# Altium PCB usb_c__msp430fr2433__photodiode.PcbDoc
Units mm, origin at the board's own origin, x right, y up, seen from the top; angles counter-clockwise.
Board outline 56 x 30 mm, 2 copper layers (Top, Bottom), stack 0 mm thick; 27 components, 18 nets, 131 pads, 47 vias.
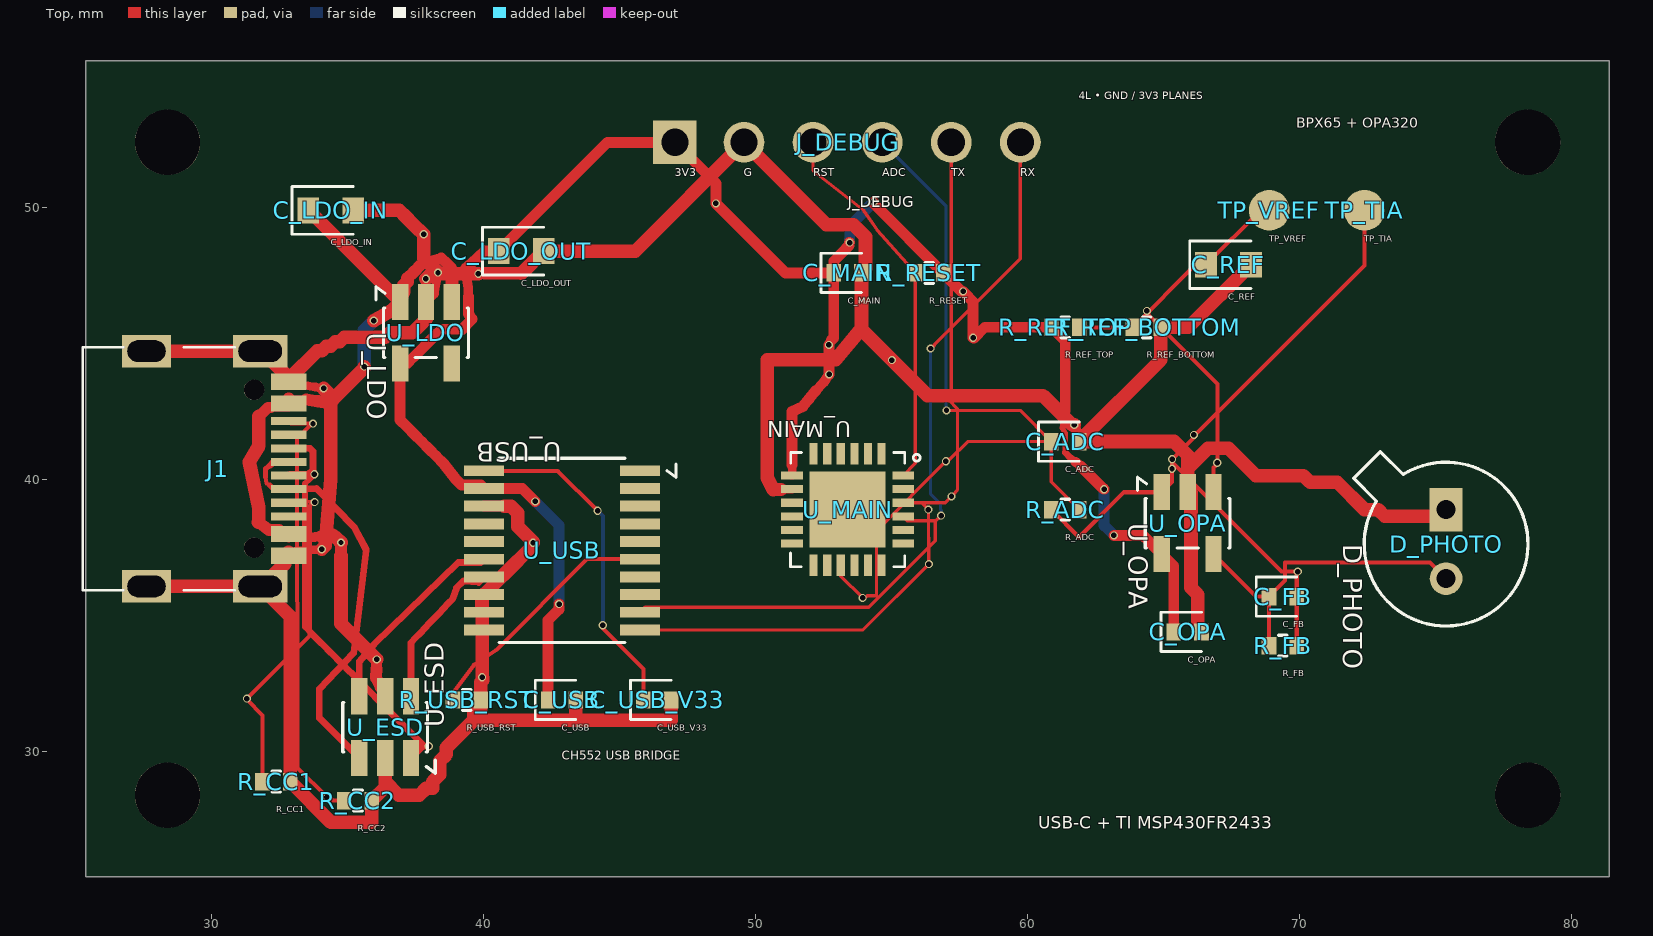
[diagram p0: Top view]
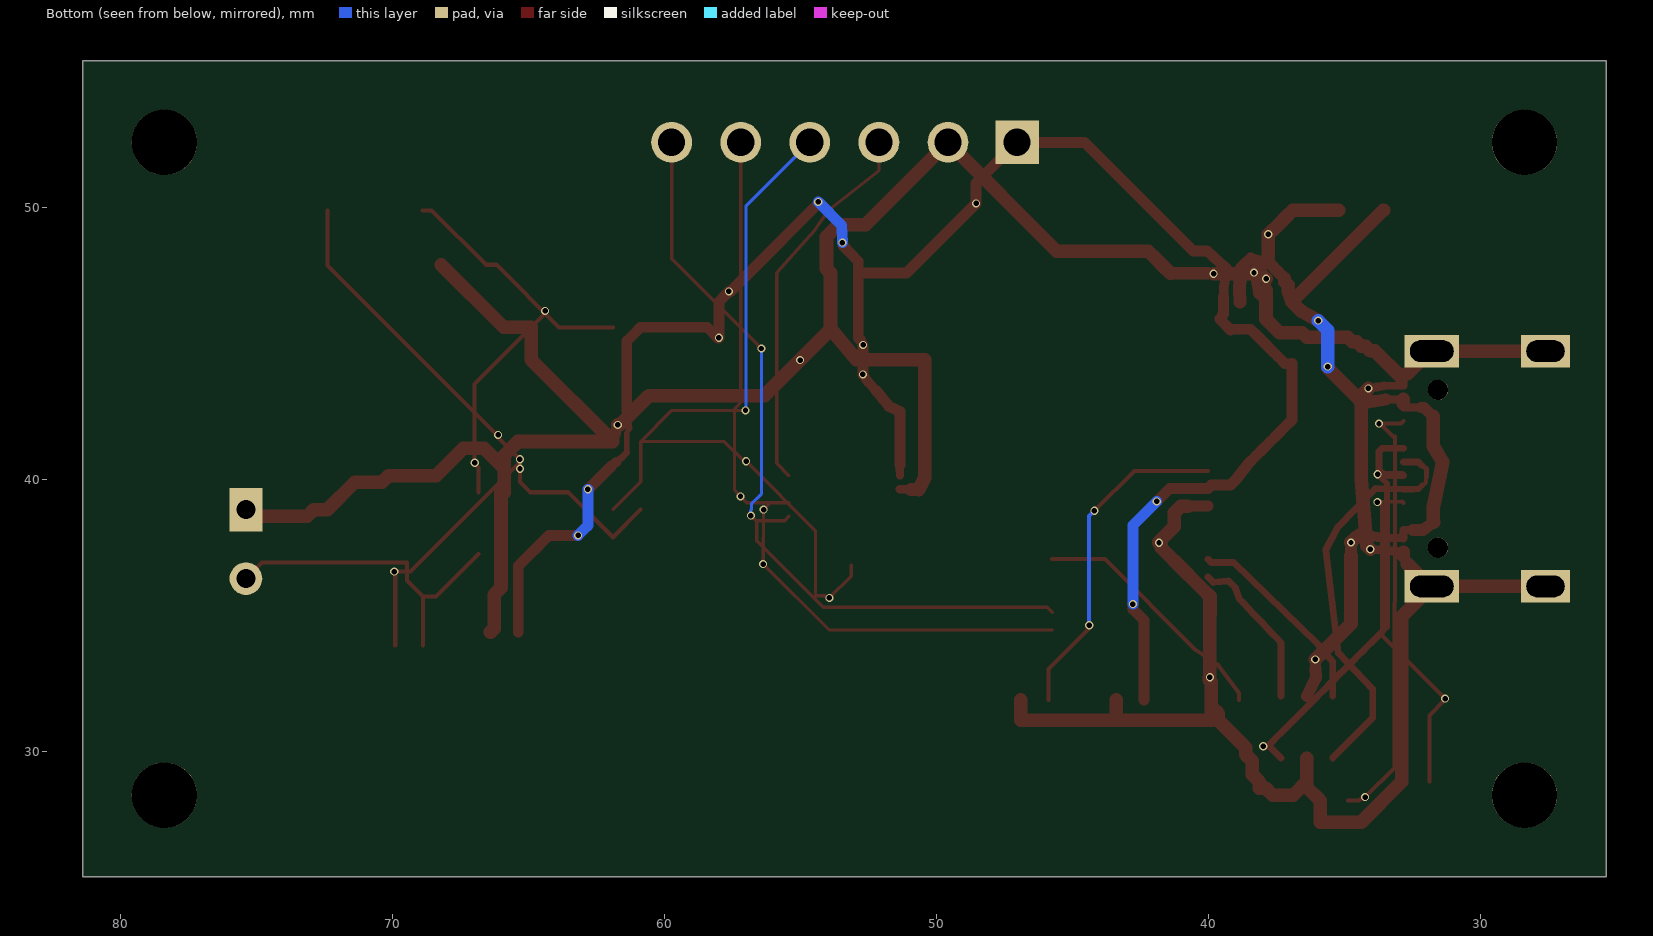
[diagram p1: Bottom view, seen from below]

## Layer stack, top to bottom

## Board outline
25.4,55.4 81.4,55.4 81.4,25.4 25.4,25.4

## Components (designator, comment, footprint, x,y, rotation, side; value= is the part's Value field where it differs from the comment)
C_ADC "" TSCIRCUIT-1.5600x0.6400mm 61.4,41.4 r0 top
C_FB "" TSCIRCUIT-1.5600x0.6400mm 69.4,35.7 r0 top
C_LDO_IN "" TSCIRCUIT-2.4500x0.9500mm 34.4,49.9 r0 top
C_LDO_OUT "" TSCIRCUIT-2.4500x0.9500mm 41.4,48.4 r0 top
C_MAIN "" TSCIRCUIT-1.5600x0.6400mm 53.4,47.6 r0 top
C_OPA "" TSCIRCUIT-1.5600x0.6400mm 65.9,34.4 r0 top
C_REF "" TSCIRCUIT-2.4500x0.9500mm 67.4,47.9 r0 top
C_USB "" TSCIRCUIT-1.5600x0.6400mm 42.9,31.9 r0 top
C_USB_V33 "" TSCIRCUIT-1.5600x0.6400mm 46.4,31.9 r0 top
D_PHOTO "" TSCIRCUIT-1.2000x3.9400mm 75.4,37.73 r270 top
J1 "" TSCIRCUIT-6.7732x9.8502mm 30.113,40.4 r90 top
J_DEBUG "" TSCIRCUIT-14.2000x1.5000mm 53.4,52.4 r0 top
R_ADC "" TSCIRCUIT-1.5600x0.6400mm 61.4,38.9 r0 top
R_CC1 "" TSCIRCUIT-1.5600x0.6400mm 32.4,28.9 r0 top
R_CC2 "" TSCIRCUIT-1.5600x0.6400mm 35.4,28.2 r0 top
R_FB "" TSCIRCUIT-1.5600x0.6400mm 69.4,33.9 r0 top
R_REF_BOTTOM "" TSCIRCUIT-1.5600x0.6400mm 64.4,45.6 r0 top
R_REF_TOP "" TSCIRCUIT-1.5600x0.6400mm 61.4,45.6 r0 top
R_RESET "" TSCIRCUIT-1.5600x0.6400mm 56.4,47.6 r0 top
R_USB_RST "" TSCIRCUIT-1.5600x0.6400mm 39.4,31.9 r0 top
TP_TIA "" TSCIRCUIT-1.5000x1.5000mm 72.4,49.9 r0 top
TP_VREF "" TSCIRCUIT-1.5000x1.5000mm 68.9,49.9 r0 top
U_ESD "" TSCIRCUIT-2.5000x3.6000mm#1 36.4,30.9 r90 top
U_LDO "" TSCIRCUIT-2.5000x3.6000mm#2 37.9,45.4 r270 top
U_MAIN "" TSCIRCUIT-4.8833x4.8963mm 53.4,38.9 r180 top
U_OPA "" TSCIRCUIT-2.5000x3.6000mm#2 65.9,38.4 r270 top
U_USB "" TSCIRCUIT-7.2000x6.2500mm 42.9,37.4 r180 top

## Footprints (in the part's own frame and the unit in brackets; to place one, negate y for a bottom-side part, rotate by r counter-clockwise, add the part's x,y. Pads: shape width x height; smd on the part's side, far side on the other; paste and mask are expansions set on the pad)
TSCIRCUIT-1.2000x3.9400mm [mm]
  rect 1.6x1.2 hole 0.7: 1(-1.17,0)
  round 1.2 hole 0.7: 2(1.37,0)
  silkscreen extent -3.3,-3.4 3.11,3.01
TSCIRCUIT-1.5000x1.5000mm [mm]
  round 1.5 smd: 1(0,0)
TSCIRCUIT-1.5600x0.6400mm [mm]
  rect 0.54x0.64 smd: 1(-0.51,0) 2(0.51,0)
  silkscreen extent -0.98,-0.72 0.51,0.72
TSCIRCUIT-2.4500x0.9500mm [mm]
  rect 0.8x0.95 smd: 1(-0.825,0) 2(0.825,0)
  silkscreen extent -1.43,-0.87 0.82,0.87
TSCIRCUIT-2.5000x3.6000mm#1 [mm]
  rect 1.325x0.6 smd: 1(-1.137,-0.95) 2(-1.137,0) 3(-1.137,0.95) 4(1.138,0.95) 5(1.138,0) 6(1.138,-0.95)
  silkscreen extent -1.69,-1.84 0.91,1.56
TSCIRCUIT-2.5000x3.6000mm#2 [mm]
  rect 1.325x0.6 smd: 1(-1.137,-0.95) 2(-1.137,0) 3(-1.137,0.95) 4(1.138,0.95) 5(1.138,-0.95)
  silkscreen extent -1.69,-1.84 0.91,1.56
TSCIRCUIT-4.8833x4.8963mm [mm]
  rect 0.8x0.3 smd: 1(-2.042,-1.25) 2(-2.042,-0.75) 3(-2.042,-0.25) 4(-2.042,0.25) 5(-2.042,0.75) 6(-2.042,1.25) 13(2.042,1.25) 14(2.042,0.75) 15(2.042,0.25) 16(2.042,-0.25) 17(2.042,-0.75) 18(2.042,-1.25)
  rect 0.3x0.8 smd: 7(-1.25,2.048) 8(-0.75,2.048) 9(-0.25,2.048) 10(0.25,2.048) 11(0.75,2.048) 12(1.25,2.048) 19(1.25,-2.048) 20(0.75,-2.048) 21(0.25,-2.048) 22(-0.25,-2.048) 23(-0.75,-2.048) 24(-1.25,-2.048)
  rect 2.8x2.8 smd: 25(-0.001,0.001)
  silkscreen extent -2.67,-2.1 2.1,2.1
TSCIRCUIT-6.7732x9.8502mm [mm]
  rect 0.3x1.3 smd: 1(-3.35,-2.737) 2(-3.05,-2.737) 3(-2.55,-2.737) 4(-2.25,-2.737) 5(-1.75,-2.737) 6(-1.25,-2.737) 7(-0.75,-2.737) 8(-0.25,-2.737) 9(0.25,-2.737) 10(0.75,-2.737) 11(1.25,-2.737) 12(1.75,-2.737) 13(2.55,-2.737) 14(2.25,-2.737) 15(3.35,-2.737) 16(3.05,-2.737)
  rect 1.2x2 hole 0.8 slot 1.6 at 90 deg: 17(-4.325,-1.693) 18(4.325,-1.693)
  rect 1.2x1.8 hole 0.8 slot 1.4 at 90 deg: 19(4.325,2.487) 20(-4.325,2.487)
  round 0.75 hole 0.75 unplated: NPTH-1(-2.9,-1.468) NPTH-2(2.9,-1.468)
  silkscreen extent -4.47,-0.75 4.47,4.83
TSCIRCUIT-7.2000x6.2500mm [mm]
  rect 1.475x0.4 smd: 1(-2.862,-2.925) 2(-2.862,-2.275) 3(-2.862,-1.625) 4(-2.862,-0.975) 5(-2.862,-0.325) 6(-2.862,0.325) 7(-2.862,0.975) 8(-2.862,1.625) 9(-2.862,2.275) 10(-2.862,2.925) 11(2.863,2.925) 12(2.863,2.275) 13(2.863,1.625) 14(2.863,0.975) 15(2.863,0.325) 16(2.863,-0.325) 17(2.863,-0.975) 18(2.863,-1.625) 19(2.863,-2.275) 20(2.863,-2.925)
  silkscreen extent -4.19,-3.39 2.31,3.38
TSCIRCUIT-14.2000x1.5000mm [mm]
  rect 1.6x1.6 hole 1: 1(-6.35,0)
  round 1.5 hole 1: 2(-3.81,0) 3(-1.27,0) 4(1.27,0) 5(3.81,0) 6(6.35,0)

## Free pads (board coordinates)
  round 2.4 hole 2.4 unplated: NPTH-3(28.4,28.4) NPTH-4(78.4,52.4) NPTH-5(78.4,28.4) NPTH-6(28.4,52.4)

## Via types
v1: diameter 0.3, hole 0.2, Top to Bottom, 47 vias

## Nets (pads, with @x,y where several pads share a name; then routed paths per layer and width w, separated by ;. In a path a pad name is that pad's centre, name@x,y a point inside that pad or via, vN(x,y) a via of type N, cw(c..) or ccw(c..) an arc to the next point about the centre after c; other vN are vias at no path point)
ADC_IN: C_ADC.1 J_DEBUG.4 R_ADC.2 U_MAIN.10 | length 30.3
  Top w0.12: U_MAIN.10 53.15,36.452 v1(53.95,35.652) 54.043,35.652 54.12,35.729 54.465,35.729 54.465,38.126 v1(57.012,40.673) 57.088,40.749 57.16,40.749 57.811,41.4 C_ADC.1 ; v1(57.034,42.544) 59.746,42.544 C_ADC.1 ; R_ADC.2 60.89,39.92 C_ADC.1
  Bottom w0.12: J_DEBUG.4 57.02,50.05 57.02,42.624 57.02,42.558 v1(57.034,42.544)
GND: C_ADC.2 C_LDO_IN.2 C_LDO_OUT.2 C_MAIN.2 C_OPA.2 C_REF.2 C_USB.2 C_USB_V33.2 D_PHOTO.1 J1.1 J1.2 J1.15 J1.16 J1.17 J1.18 J1.19 J1.20 J_DEBUG.2 R_CC1.2 R_CC2.2 R_REF_BOTTOM.2 R_USB_RST.2 U_ESD.2 U_LDO.2 U_MAIN.17 U_OPA.2 U_USB.18 | length 150.8
  Top w0.275: J1.16 33.197,43.45 33.545,43.45
  Top w0.288: J1.16 J1.16@32.849,43.6
  Top w0.3: J1.1@32.699,36.9 J1.1 J1.1@32.849,37.2 ; 32.699,43.9 J1.15 ; J1.16@32.849,43.6 J1.15 ; J1.15@32.917,43.75 J1.15
  Top w0.312: 33.545,43.45 33.841,43.401 ; v1(39.828,47.57) 40.062,47.587
  Top w0.318: U_MAIN.17@50.958,39.641 51.012,39.642 U_MAIN.17
  Top w0.325: J1.2 33.256,37.38 33.664,37.41 v1(34.071,37.44) ; 33.841,43.401 v1(34.137,43.351) ; 38.2,46.837 38.271,47.224 v1(38.343,47.611)
  Top w0.35: v1(37.899,47.384) 37.899,46.962 U_LDO.2@37.9,46.961 ; U_LDO.2 38.2,46.837
  Top w0.4: U_USB.18 U_USB.18@40.775,39.025 ; v1(61.73,42.012) 61.82,41.706 C_ADC.2
  Top w0.475: J1.1@32.849,37.2 J1.2 ; 40.062,47.587 40.512,47.587 40.962,47.587 41.412,47.587 ; 50.666,39.634 U_MAIN.17@50.958,39.641
  Top w0.5: J1.20 J1.17 ; J1.19 J1.18 31.874,44.725 32.474,44.125 32.699,43.9 ; J1.1@32.699,36.9 32.474,36.675 31.874,36.075 J1.17 ; J1.15@32.917,43.75 33.9,44.733 34.067,44.733 34.233,44.9 34.4,44.9 34.567,45.067 34.733,45.067 34.9,45.233 36.4,45.233 36.567,45.4 37.4,45.4 37.9,45.9 U_LDO.2 U_LDO.2@37.9,46.961 ; v1(34.071,37.44) 34.2,37.569 34.2,37.6 34.4,40 34.4,43.089 v1(34.137,43.351) ; C_LDO_IN.2 35.647,49.9 36.07,49.9 36.492,49.9 36.915,49.9 37.165,49.65 37.415,49.4 37.664,49.15 37.687,49.15 v1(37.815,49.022) 37.815,48.139 v1(38.343,47.611) ; v1(37.899,47.384) 38.085,47.57 v1(39.828,47.57) ; 40.775,39.025 41.025,39.025 41.275,38.775 41.275,38.275 41.834,37.716 v1(41.834,37.68) 41.753,37.599 41.753,37.5 41.454,37.201 41.155,36.902 40.856,36.602 40.557,36.303 40.258,36.004 39.959,35.705 39.96,35.211 39.961,34.716 39.962,34.222 39.963,33.727 39.964,33.233 v1(39.965,32.738) 39.981,32.722 39.981,32.62 39.91,32.55 39.91,32.225 R_USB_RST.2 ; 41.412,47.587 41.683,47.858 41.954,48.129 C_LDO_OUT.2 45.59,48.4 J_DEBUG.2 52.621,49.369 53.619,49.369 54.056,48.931 54.056,48.275 54.056,47.746 C_MAIN.2 ; C_USB_V33.2 46.91,31.15 43.41,31.15 ; 50.666,39.634 50.447,40.072 50.447,44.41 52.963,44.41 53.91,45.556 53.91,45.965 53.91,46.374 53.91,46.783 53.91,47.191 C_MAIN.2 ; v1(61.73,42.012) 61.656,42.012 60.578,43.089 56.337,43.089 v1(55.03,44.396) 53.91,45.516 C_MAIN.2 ; C_OPA.2 66.4,34.4 66.275,34.525 66.275,35.775 66.025,36.025 66.025,39.525 65.912,39.525 U_OPA.2 ; C_REF.2 65.925,45.6 R_REF_BOTTOM.2 64.91,44.4 C_ADC.2 65.4,41.4 65.9,40.9 U_OPA.2 ; D_PHOTO.1 75.152,38.652 74.654,38.652 74.155,38.652 73.656,38.652 73.158,38.652 73.148,38.652 72.9,38.9 72.4,38.9 71.4,39.9 70.4,39.9 70.15,40.15 68.4,40.15 67.4,41.15 66.65,41.15 65.9,40.4 U_OPA.2 ; J1.17 32.91,34.971 R_CC1.2 34.41,27.4 35.91,27.4 R_CC2.2 36.4,28.69 U_ESD.2 36.4,28.9 36.9,28.4 37.65,28.4 37.9,28.65 38.15,28.65 38.15,28.9 38.4,29.15 38.4,29.65 38.65,29.9 38.65,30.15 39.65,31.15 39.65,31.4 39.91,31.66 R_USB_RST.2 ; R_USB_RST.2 39.91,31.15 43.41,31.15 ; 43.41,31.15 C_USB.2 43.41,31.15
MAIN_RESET: J_DEBUG.3 R_RESET.1 U_MAIN.1 | length 14
  Top w0.12: J_DEBUG.3 52.13,51.36 53.981,49.904 54.486,49.17 R_RESET.1 55.89,40.598 U_MAIN.1
PD_SUM: C_FB.1 D_PHOTO.2 R_FB.1 U_OPA.4 | length 12.2
  Top w0.15: U_OPA.4 68.412,35.7 C_FB.1 ; R_FB.1 C_FB.1 ; D_PHOTO.2 74.804,36.956 69.479,36.96 69.479,36.289 C_FB.1
TIA_OUT: C_FB.2 R_ADC.1 R_FB.2 TP_TIA.1 U_OPA.1 | length 29.1
  Top w0.15: R_ADC.1 61.908,37.882 63.564,39.538 U_OPA.1 ; R_FB.2 C_FB.2 69.91,36.45 69.91,36.584 v1(69.95,36.619) 69.35,36.624 65.344,40.63 65.344,40.736 v1(65.325,40.4) 65.33,39.917 ; TP_TIA.1 72.4,47.873 66.24,41.713 66.202,41.713 v1(66.131,41.642) 66.131,41.551 65.34,40.76 v1(65.33,40.75) 65.33,39.917 ; U_OPA.1 65.33,39.917 ; U_OPA.1 65.33,39.917
UART_MAIN_RX: J_DEBUG.6 U_MAIN.4 U_USB.9 | length 30.7
  Top w0.12: U_USB.9 45.949,35.311 54.181,35.311 56.626,37.757 56.626,38.492 55.6,38.492 U_MAIN.4 55.615,38.477 55.619,38.477 56.619,38.477 v1(56.835,38.677) ; v1(56.451,44.82) 56.588,44.927 56.588,44.96 59.75,48.121 J_DEBUG.6
  Bottom w0.12: v1(56.451,44.82) 56.451,39.47 56.817,39.103 56.817,38.9 56.85,38.868 56.85,38.708 v1(56.835,38.677)
UART_MAIN_TX: J_DEBUG.5 U_MAIN.3 U_USB.10 | length 29.7
  Top w0.12: U_USB.10 53.966,34.475 v1(56.387,36.896) ; v1@56.388,36.898 56.383,36.903 v1(56.371,38.9) 56.349,38.928 56.127,39.15 U_MAIN.3 56.985,39.15 v1(57.219,39.384) 57.349,39.514 57.349,39.529 57.435,39.615 57.435,39.744 57.435,42.611 57.342,42.705 57.21,42.836 J_DEBUG.5
USB_BRIDGE_RESET: R_USB_RST.1 U_USB.6 | length 9.2
  Top w0.15: R_USB_RST.1 38.887,32.142 39.675,33.2 40.484,33.737 43.825,37.075 U_USB.6
USB_BRIDGE_V33: C_USB_V33.1 U_USB.20 | length 12.4
  Top w0.15: U_USB.20 42.743,40.325 v1(44.211,38.857) ; v1(44.4,34.646) 44.4,34.533 45.89,33.043 C_USB_V33.1
  Bottom w0.15: v1(44.211,38.857) 44.234,38.834 44.234,38.826 44.4,38.661 v1(44.4,34.646)
USB_CC1: J1.6 R_CC1.1 | length 12.6
  Top w0.15: R_CC1.1 31.89,31.333 31.312,31.91 31.312,31.945 v1(31.319,31.952) 33.626,34.259 33.626,39.013 33.626,39.026 33.782,39.182 v1(33.808,39.176) 32.899,39.2 J1.6
USB_CC2: J1.12 R_CC2.1 | length 16.1
  Top w0.15: J1.12 32.938,42.061 v1(33.746,42.061) 33.735,42.05 33.69,42.05 33.231,41.591 33.165,41.591 33.179,29.401 v1(34.26,28.33) 34.325,28.265 34.417,28.265 34.482,28.2 R_CC2.1
USB_DM_MCU: U_ESD.4 U_USB.15 | length 7.4
  Top w0.25: U_ESD.4 35.449,33.31 36,33.95 39.086,36.956 39.916,36.954 U_USB.15
USB_DM_PORT: J1.7 J1.9 U_ESD.3 | length 15.1
  Top w0.156: 32,40.1 32.037,39.865 32.157,39.789
  Top w0.188: 32,40.1 32.003,40.2 32,40.4 32.176,40.529
  Top w0.2: 32.157,39.789 J1.7@32.296,39.65
  Top w0.225: J1.7@32.296,39.65 J1.7@32.48,39.65
  Top w0.25: 32.176,40.529 32.297,40.65 32.481,40.65 32.665,40.65 J1.9 ; J1.7@32.48,39.65 32.665,39.65 J1.7 33.87,39.67 35.267,38.24 35.704,37.424 35.241,33.621 33.978,32.307 33.978,31.234 U_ESD.3
USB_DP_MCU: U_ESD.6 U_USB.14 | length 5.8
  Top w0.25: U_ESD.6 37.35,32.283 37.35,32.529 37.35,32.775 37.35,33.021 37.35,33.267 37.35,33.513 37.35,33.759 37.35,34.005 37.521,34.185 37.691,34.364 37.862,34.544 38.033,34.724 38.204,34.903 38.374,35.083 38.545,35.262 38.716,35.442 38.887,35.621 39.025,36.025 39.275,36.275 39.836,36.224 39.937,36.324 U_USB.14
USB_DP_PORT: J1.8 J1.10 U_ESD.1 | length 16.5
  Top w0.212: 33.459,34.582 33.456,34.595 33.456,34.834 33.456,35.073 33.456,35.312 33.455,35.551 33.455,35.79 33.455,36.029 33.454,36.268 33.454,36.507 33.454,36.747 33.453,36.986 33.453,37.225 33.453,37.464 33.452,37.703 33.452,37.942 33.452,38.181 33.451,38.42 33.451,38.659 33.451,38.898 33.45,39.137 33.45,39.376 33.45,39.615 33.449,39.854 33.625,40.027 v1(33.8,40.2)
  Top w0.219: 33.459,34.582 33.634,34.407
  Top w0.25: J1.10 33.637,41.15 33.746,41.042 33.746,40.359 33.587,40.2 32.899,40.2 J1.8 33.099,40.15 33.349,40.15 33.599,40.15 33.75,40.15 v1(33.8,40.2) ; 33.634,34.407 33.809,34.232 33.984,34.056 34.16,33.881 34.335,33.706 34.51,33.531 34.685,33.355 34.86,33.18 35.035,33.005 35.21,32.829 35.385,32.654 35.56,32.479 35.736,32.304 35.911,32.128 36.086,31.953 36.261,31.778 36.436,31.602 36.611,31.427 36.786,31.252 36.961,31.076 37.136,30.901 37.312,30.726 37.487,30.551 37.662,30.375 37.837,30.2 v1(38,30.2) 37.788,30.2 37.642,30.054 37.496,29.908 U_ESD.1
VBUS5: C_LDO_IN.1 J1.3 J1.4 J1.13 J1.14 U_ESD.5 U_LDO.1 U_LDO.3 | length 30.8
  Top w0.3: J1.14@32.199,42.65 J1.14 J1.14@32.849,42.8 ; J1.4@32.491,38.15 J1.4 J1.3@32.849,38 ; J1.3 32.945,37.861 33.037,37.85 33.13,37.85 33.224,37.85 33.318,37.85 33.412,37.85 33.499,37.85 ; J1.13 32.943,42.95 33.037,42.95 33.13,42.95 33.224,42.95 33.318,42.95 33.412,42.95 33.499,42.95
  Top w0.31: J1.3 J1.3@32.849,38
  Top w0.375: 33.499,37.85 33.505,37.85 33.984,37.906
  Top w0.4: 31.757,42.32 31.838,42.4 32.087,42.65 J1.14@32.199,42.65 ; 33.984,37.906 34.462,37.962 ; 36.079,33.053 v1(36.087,33.391) ; 37.713,47.9 38.088,48.025 38.463,48.15 38.65,47.962 38.837,47.775 38.858,47.384
  Top w0.425: 34.775,37.196 v1(34.775,37.689)
  Top w0.437: 31.744,38.431 32.134,38.15 J1.4@32.491,38.15 ; 36.079,33.053 36.07,32.714 36.235,32.376 U_ESD.5 ; 37.213,47.4 37.463,47.65 37.713,47.9
  Top w0.45: 33.499,42.95 33.505,42.95 33.937,42.878 34.369,42.806 ; 37.213,47.275 37.213,47.4
  Top w0.475: U_LDO.3 38.878,46.992 38.858,47.384
  Top w0.5: 31.744,38.431 31.757,38.527 31.757,38.98 31.4,40.65 31.757,41.244 31.757,42.32 ; J1.13@32.849,42.8 J1.13@32.849,42.95 ; C_LDO_IN.1 33.587,49.9 U_LDO.1 ; 34.369,42.806 34.546,43.018 35.631,44.103 v1(35.631,44.154) ; 34.462,37.962 34.599,37.859 34.605,37.859 v1(34.775,37.689) ; 34.775,37.196 34.775,36.704 34.775,34.703 v1(36.087,33.391) ; v1(35.982,45.844) 36.592,46.191 36.603,46.191 U_LDO.1 ; 37.213,47.275 37.081,47.144 37.081,46.906 U_LDO.1
  Bottom w0.5: v1(35.631,44.154) 35.631,45.493 v1(35.982,45.844)
VCC_3V3: C_LDO_OUT.1 C_MAIN.1 C_OPA.1 C_USB.1 J_DEBUG.1 R_REF_TOP.1 R_RESET.2 U_LDO.5 U_MAIN.18 U_OPA.5 U_USB.19 | length 74
  Top w0.2: 61.3,41.9 61.4,41.7 61.4,41.35 61.4,41
  Top w0.212: 61.3,41.9 61.35,42.213
  Top w0.25: 61.35,42.213 61.399,42.526 ; 61.4,41 61.6,40.8 61.778,40.653
  Top w0.3: U_MAIN.18 U_MAIN.18@51.358,40.3
  Top w0.312: 51.358,40.3 51.358,40.543
  Top w0.35: 39.4,47.4 39.458,47.05 39.458,46.729
  Top w0.363: 52.236,43.281 52.5,43.55 v1(52.719,43.87) ; 61.778,40.653 61.956,40.505
  Top w0.375: v1(52.713,44.955) 52.812,45.132
  Top w0.387: 39.342,47.75 39.4,47.4
  Top w0.4: 39.342,47.75 39.583,47.967 39.824,48.183 40.066,48.4 40.32,48.4 C_LDO_OUT.1 44.575,52.4 J_DEBUG.1 48.557,50.893 v1(48.557,50.154) 48.657,50.054 51.111,47.6 C_MAIN.1 ; 39.458,46.729 39.458,46.408 39.458,46.088 39.6,45.9 39.2,45.5 39.187,45.53 38.827,45.53 38.467,45.53 38.214,45.276 37.96,45.023 37.706,44.769 37.453,44.516 37.199,44.262 U_LDO.5 36.95,43.917 36.95,43.571 36.95,43.226 36.95,42.88 36.95,42.535 36.95,42.189 37.216,41.924 37.481,41.658 37.747,41.393 38.012,41.127 38.278,40.862 38.543,40.596 39,40 39.2,39.8 39.34,39.8 39.626,39.8 39.913,39.8 U_USB.19 41.44,39.675 v1(41.916,39.199) ; C_USB.1 42.39,34.829 42.794,35.233 v1(42.794,35.424) ; 51.358,40.543 51.358,40.936 51.358,41.33 51.358,41.723 51.358,42.116 51.358,42.509 51.556,42.601 51.753,42.692 51.995,42.987 52.236,43.281 ; v1(52.713,44.955) 52.713,44.623 52.713,44.291 52.713,43.96 52.715,43.957 52.715,43.874 v1(52.719,43.87) ; 52.812,45.132 52.89,45.211 52.89,45.609 52.89,46.007 52.89,46.405 52.89,46.804 52.89,47.202 C_MAIN.1 ; v1(53.473,48.716) 53.461,48.715 53.456,48.61 52.89,48.03 C_MAIN.1 ; v1(54.36,50.209) 54.36,50.15 R_RESET.2 57.588,46.922 v1(57.645,46.922) 57.714,46.853 57.714,46.84 58.015,46.539 v1(58.015,45.216) 58.023,45.208 58.052,45.208 58.444,45.6 R_REF_TOP.1 61.145,45.345 61.4,45.09 61.4,44.724 61.4,44.358 61.4,43.991 61.4,43.625 61.4,43.259 61.4,42.893 61.399,42.526 ; 61.956,40.505 62.234,40.227 62.512,39.949 62.79,39.671 62.806,39.671 v1(62.831,39.646) ; v1(63.189,37.952) 63.546,37.952 63.903,37.952 64.26,37.952 64.49,37.722 64.72,37.492 U_OPA.5 65.39,36.822 C_OPA.1
  Bottom w0.4: v1(41.916,39.199) 42.037,39.078 42.794,38.321 v1(42.794,35.424) ; v1(53.473,48.716) 53.497,49.346 54.333,50.182 v1(54.36,50.209) ; v1(62.831,39.646) 62.831,39.314 62.831,38.982 62.831,38.651 62.831,38.319 62.98,38.17 63.129,38.021 63.129,38.012 v1(63.189,37.952)
VREF_0V5: C_REF.1 R_REF_BOTTOM.1 R_REF_TOP.2 TP_VREF.1 U_OPA.3 | length 17.4
  Top w0.15: R_REF_TOP.2 R_REF_BOTTOM.1 ; U_OPA.3 66.85,40.439 66.919,40.509 66.919,40.546 v1(66.991,40.618) 66.991,43.517 64.462,46.046 64.462,46.14 v1(64.4,46.202) 64.4,46.11 R_REF_BOTTOM.1 ; TP_VREF.1 68.575,49.9 C_REF.1 66.19,47.9 R_REF_BOTTOM.1
pads on no net: J1.5 J1.11 J1.NPTH-1 J1.NPTH-2 U_LDO.4 U_MAIN.2 U_MAIN.5 U_MAIN.6 U_MAIN.7 U_MAIN.8 U_MAIN.9 U_MAIN.11 U_MAIN.12 U_MAIN.13 U_MAIN.14 U_MAIN.15 U_MAIN.16 U_MAIN.19 U_MAIN.20 U_MAIN.21 U_MAIN.22 U_MAIN.23 U_MAIN.24 U_MAIN.25 U_USB.1 U_USB.2 U_USB.3 U_USB.4 U_USB.5 U_USB.7 U_USB.8 U_USB.11 U_USB.12 U_USB.13 U_USB.16 U_USB.17

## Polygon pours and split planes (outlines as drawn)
GND on Mid1 (solid): 81.1,55.1 25.7,55.1 25.7,25.7 81.1,25.7
VCC_3V3 on Mid2 (solid): 81.1,55.1 25.7,55.1 25.7,25.7 81.1,25.7

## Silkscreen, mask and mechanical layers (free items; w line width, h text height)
Top Overlay:
  text "4L • GND / 3V3 PLANES" at 61.9,53.9 h0.48
  text "BPX65 + OPA320" at 69.9,52.8 h0.65
  text "CH552 USB BRIDGE" at 42.9,29.6 h0.55
  text "USB-C + TI MSP430FR2433" at 60.4,27 h0.78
